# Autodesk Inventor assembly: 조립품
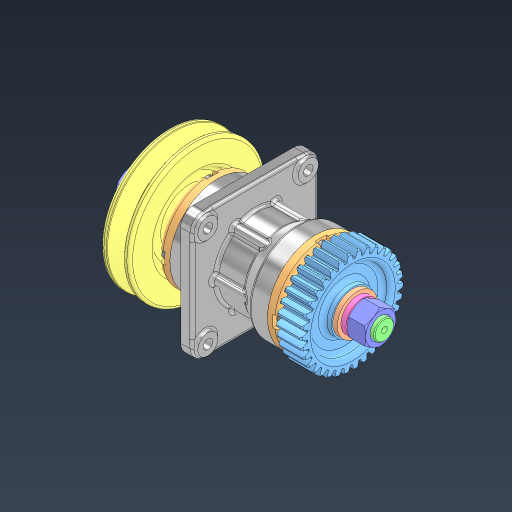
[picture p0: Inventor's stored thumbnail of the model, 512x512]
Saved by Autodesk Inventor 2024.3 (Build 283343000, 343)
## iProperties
Created: 2025-08
Part Number: 조립품
Document SubType Name: Assembly
Designer: user
Author: user
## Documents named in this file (13)
- C:\Users\user\Desktop\750803V1006\조립품.iam
- C:\Users\user\Desktop\750803V1006\본체.ipt
- C:\Users\user\Desktop\750803V1006\깊은 홈 볼 베어링 6005\깊은 홈 볼 베어링 6005\깊은 홈 볼 베어링 6005.ipt
- C:\Users\user\Desktop\750803V1006\축\축\축.ipt
- C:\Users\user\Desktop\750803V1006\커버\커버\커버.ipt
- C:\Users\user\Desktop\750803V1006\오일 실 25 38 5\오일 실 25 38 5\오일 실 25 38 5.ipt
- C:\Users\user\Desktop\750803V1006\6각 구멍붙이 볼트 M4x10\6각 구멍붙이 볼트 M4x10\6각 구멍붙이 볼트 M4x10.ipt
- C:\Users\user\Desktop\750803V1006\평행 키 6x6x14\평행 키 6x6x14\평행 키 6x6x14.ipt
- C:\Users\user\Desktop\750803V1006\V 벨트 풀리\V 벨트 풀리\V 벨트 풀리.ipt
- C:\Users\user\Desktop\750803V1006\스퍼기어\스퍼기어\스퍼기어.ipt
- C:\Users\user\Desktop\750803V1006\평 와셔 M14\평 와셔 M14\평 와셔 M14.ipt
- C:\Users\user\Desktop\750803V1006\스프링 와셔 M14\스프링 와셔 M14\스프링 와셔 M14.ipt
- C:\Users\user\Desktop\750803V1006\6각 너트 M14x1\6각 너트 M14x1\6각 너트 M14x1.ipt
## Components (11 placed, 3 different names)
1. 6각 구멍붙이 볼트 M4x10:1
2. 6각 구멍붙이 볼트 M4x10:2
3. 6각 구멍붙이 볼트 M4x10:3
4. 6각 구멍붙이 볼트 M4x10:4
5. 6각 구멍붙이 볼트 M4x10:5
6. 6각 구멍붙이 볼트 M4x10:6
7. 6각 구멍붙이 볼트 M4x10:7
8. 6각 구멍붙이 볼트 M4x10:8
9. V 벨트 풀리:1
10. 6각 너트 M14x1:1
11. 6각 너트 M14x1:2
